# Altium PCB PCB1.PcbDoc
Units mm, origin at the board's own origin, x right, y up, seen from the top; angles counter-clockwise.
Board outline 78 x 70 mm, 2 copper layers (Top Layer, Bottom Layer); 42 components, 25 nets, 126 pads, 4 vias.
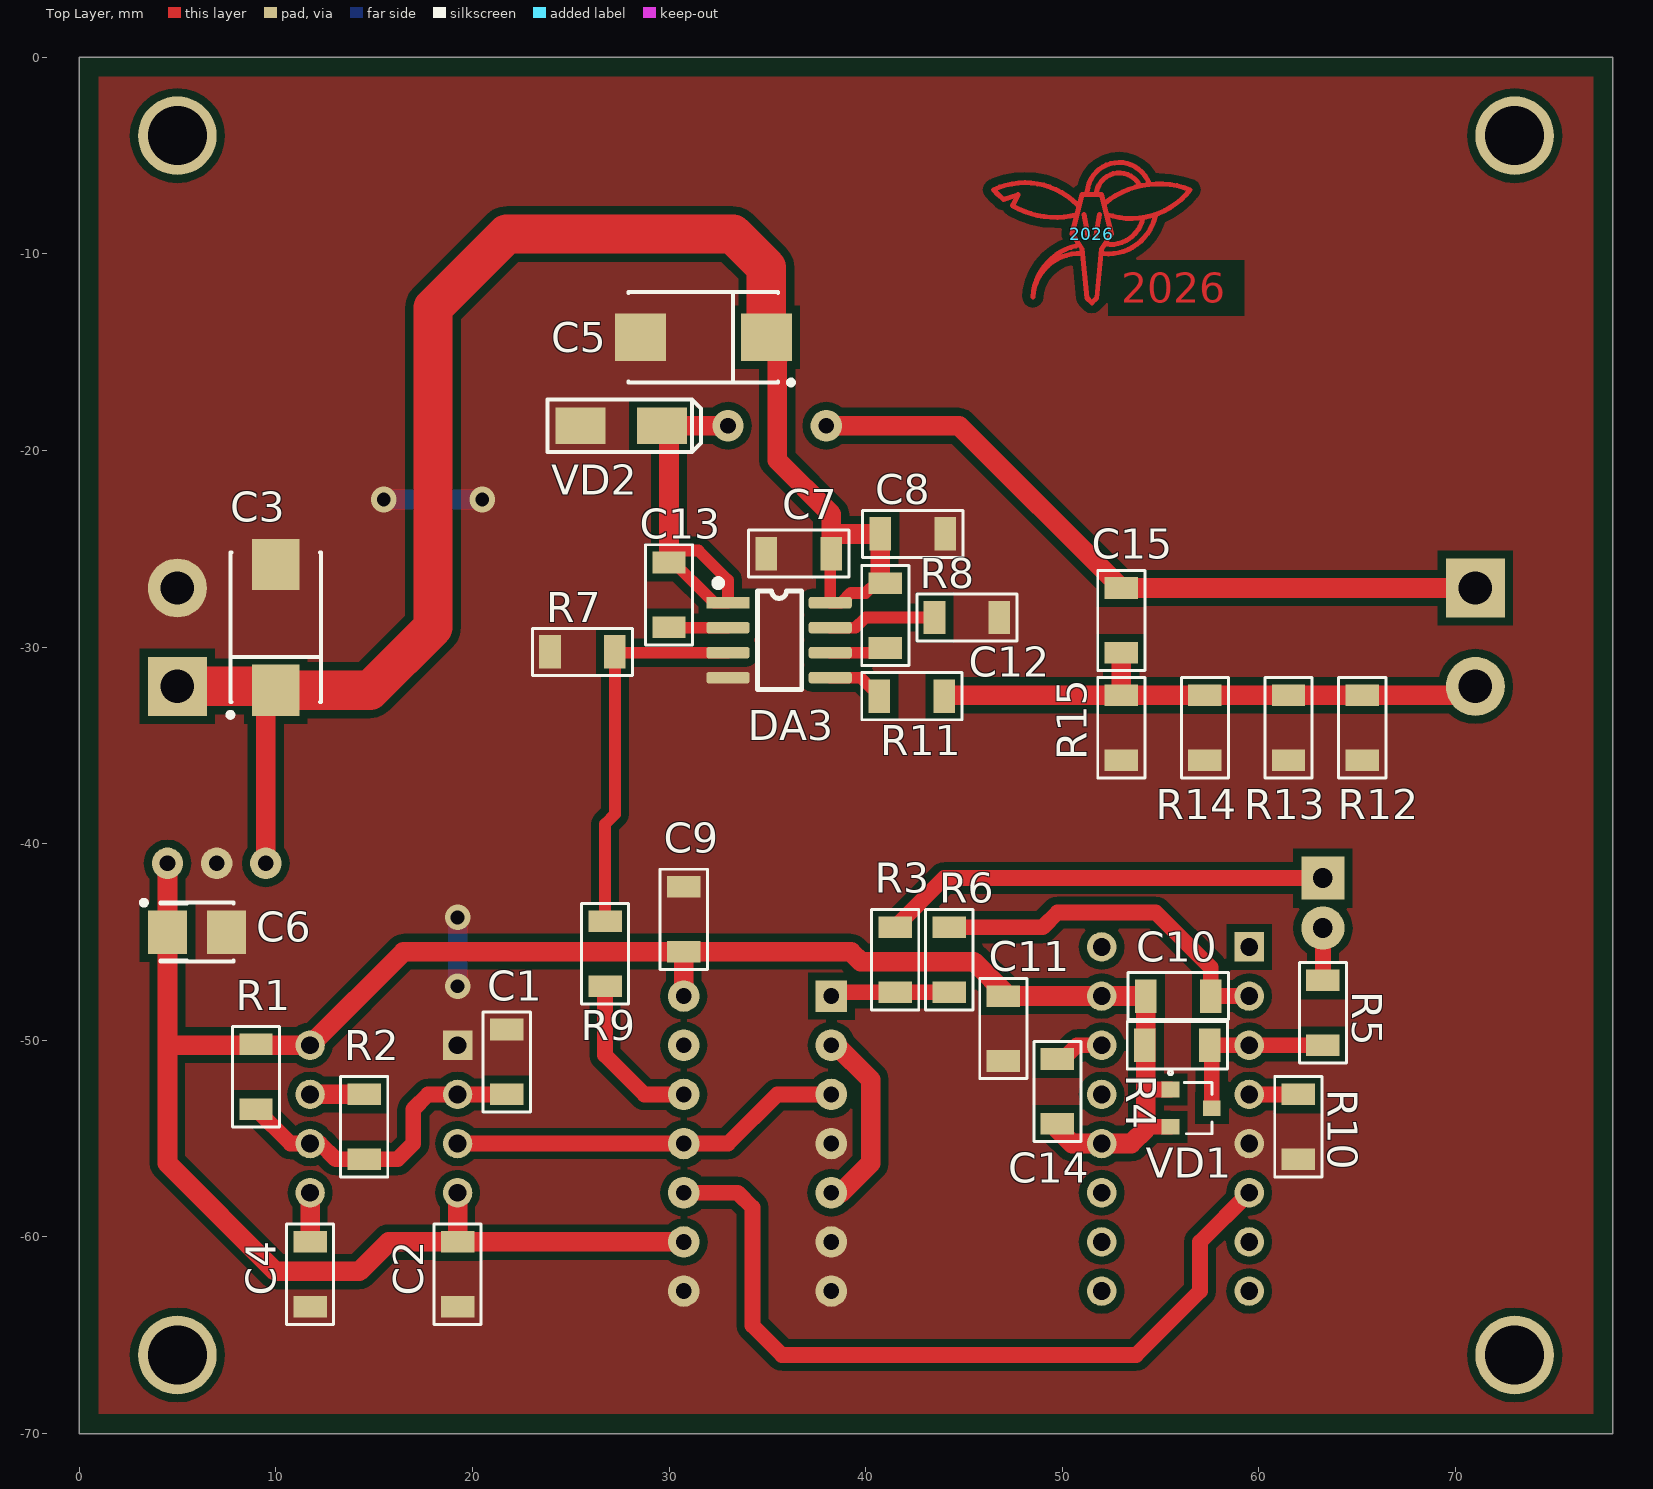
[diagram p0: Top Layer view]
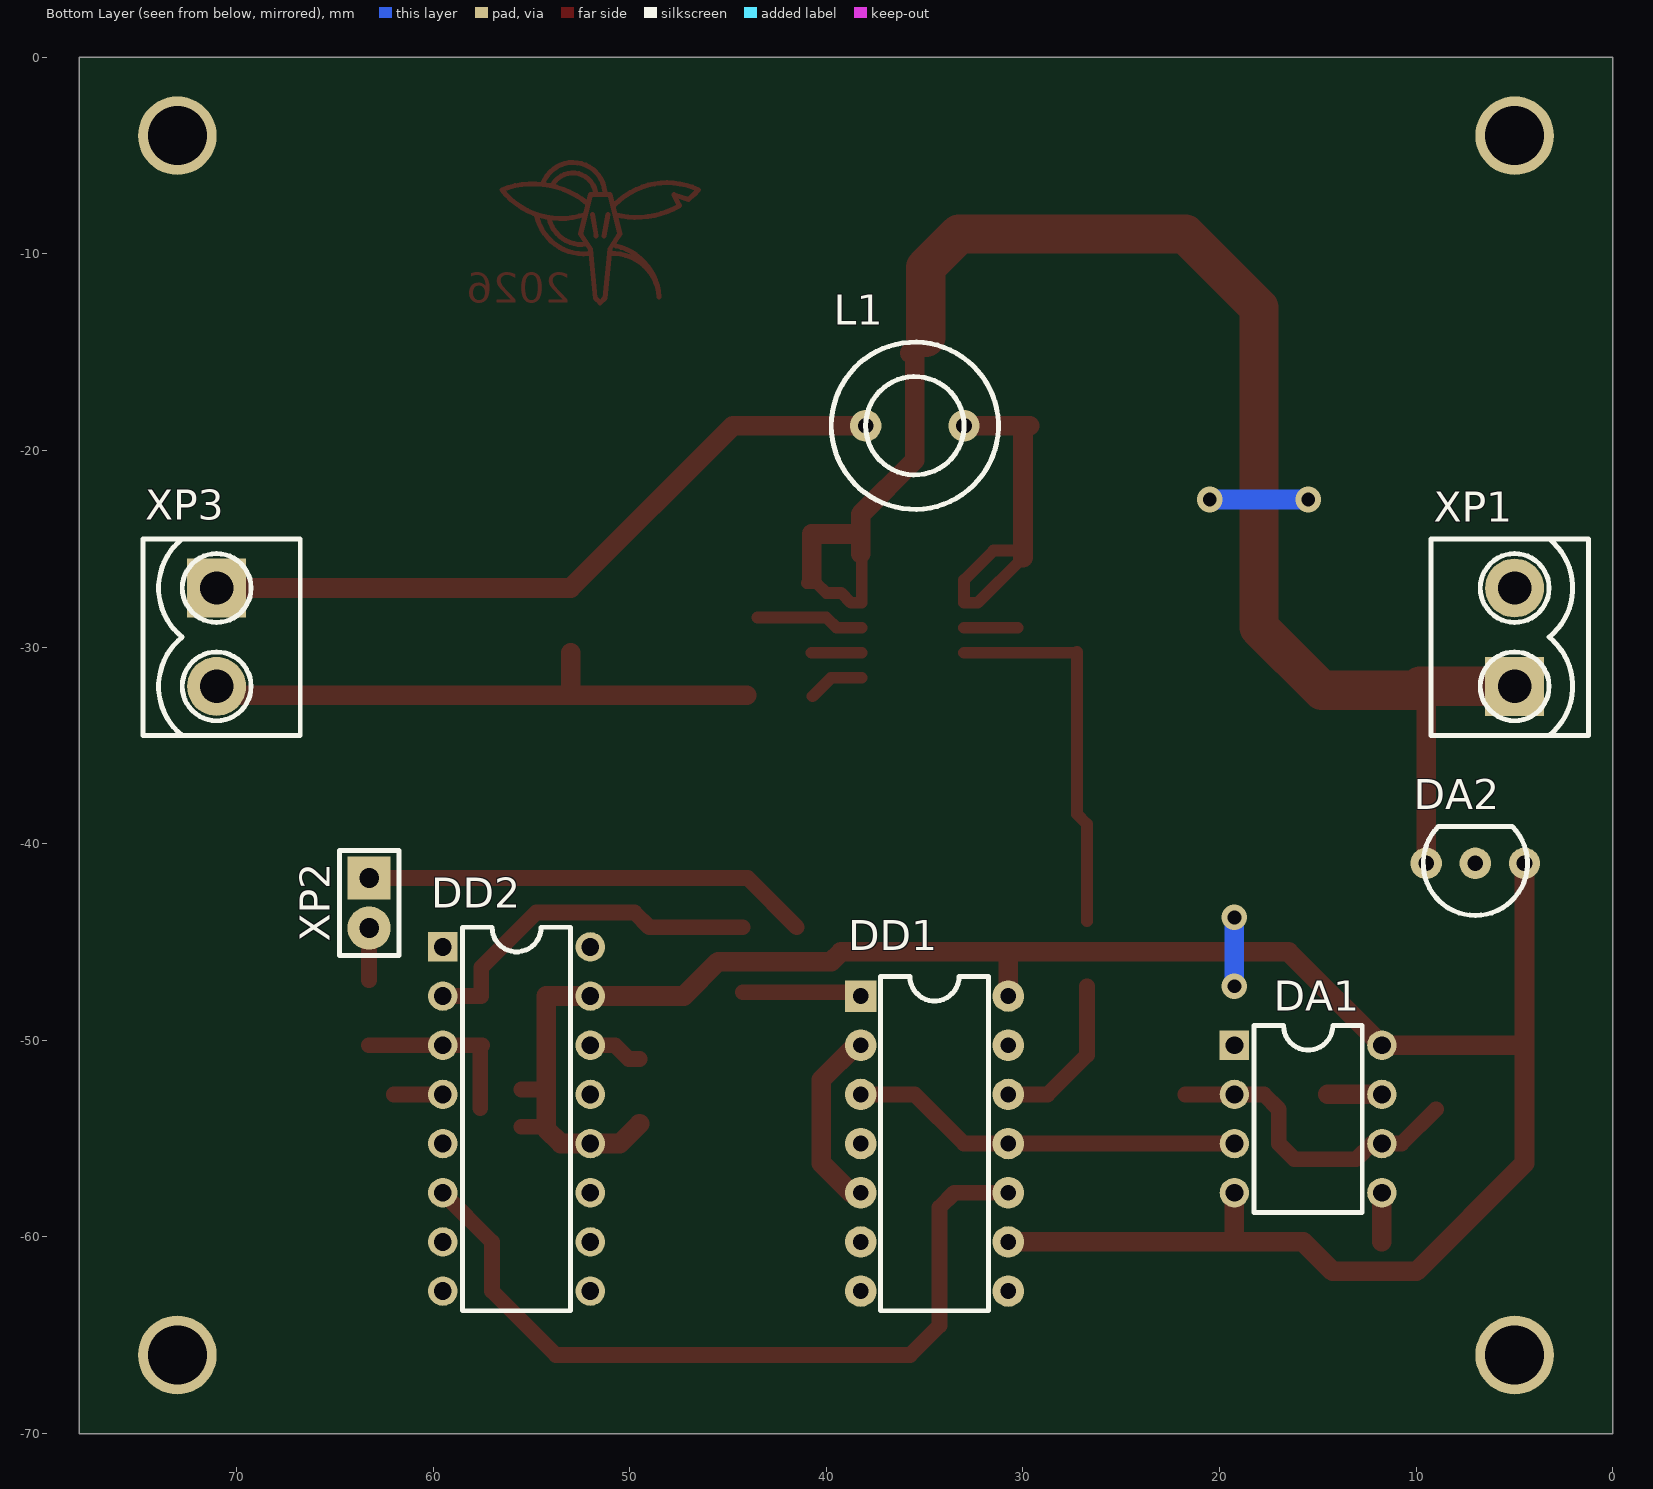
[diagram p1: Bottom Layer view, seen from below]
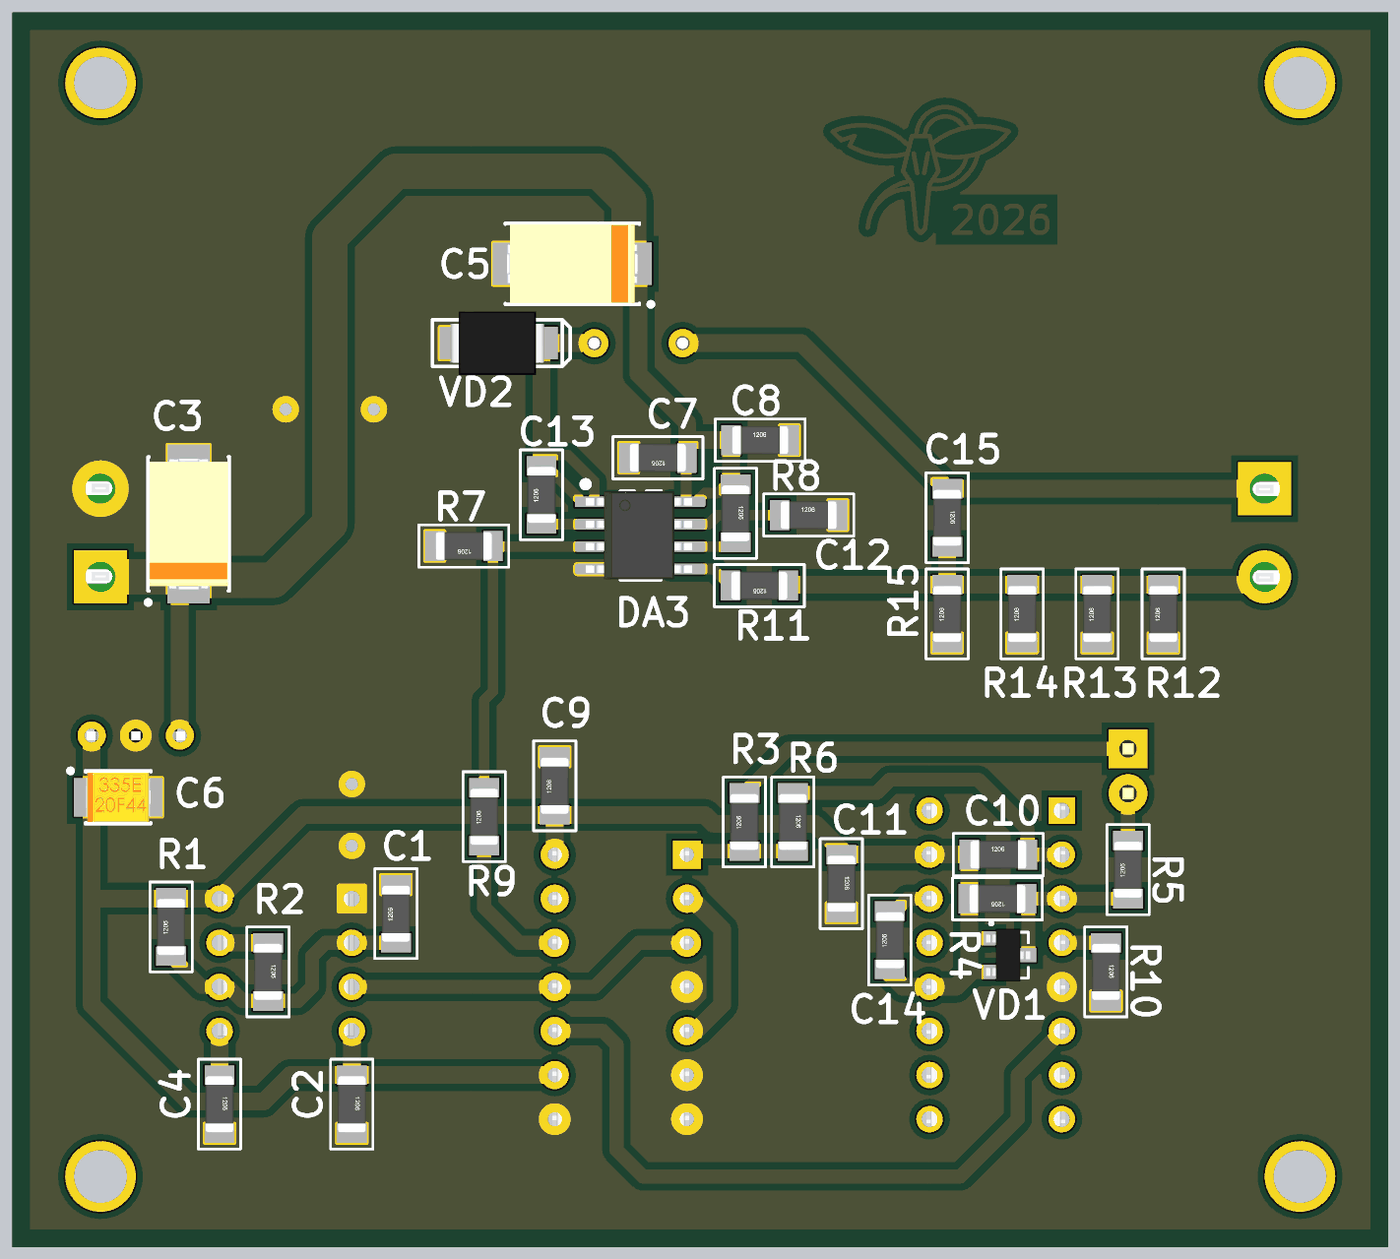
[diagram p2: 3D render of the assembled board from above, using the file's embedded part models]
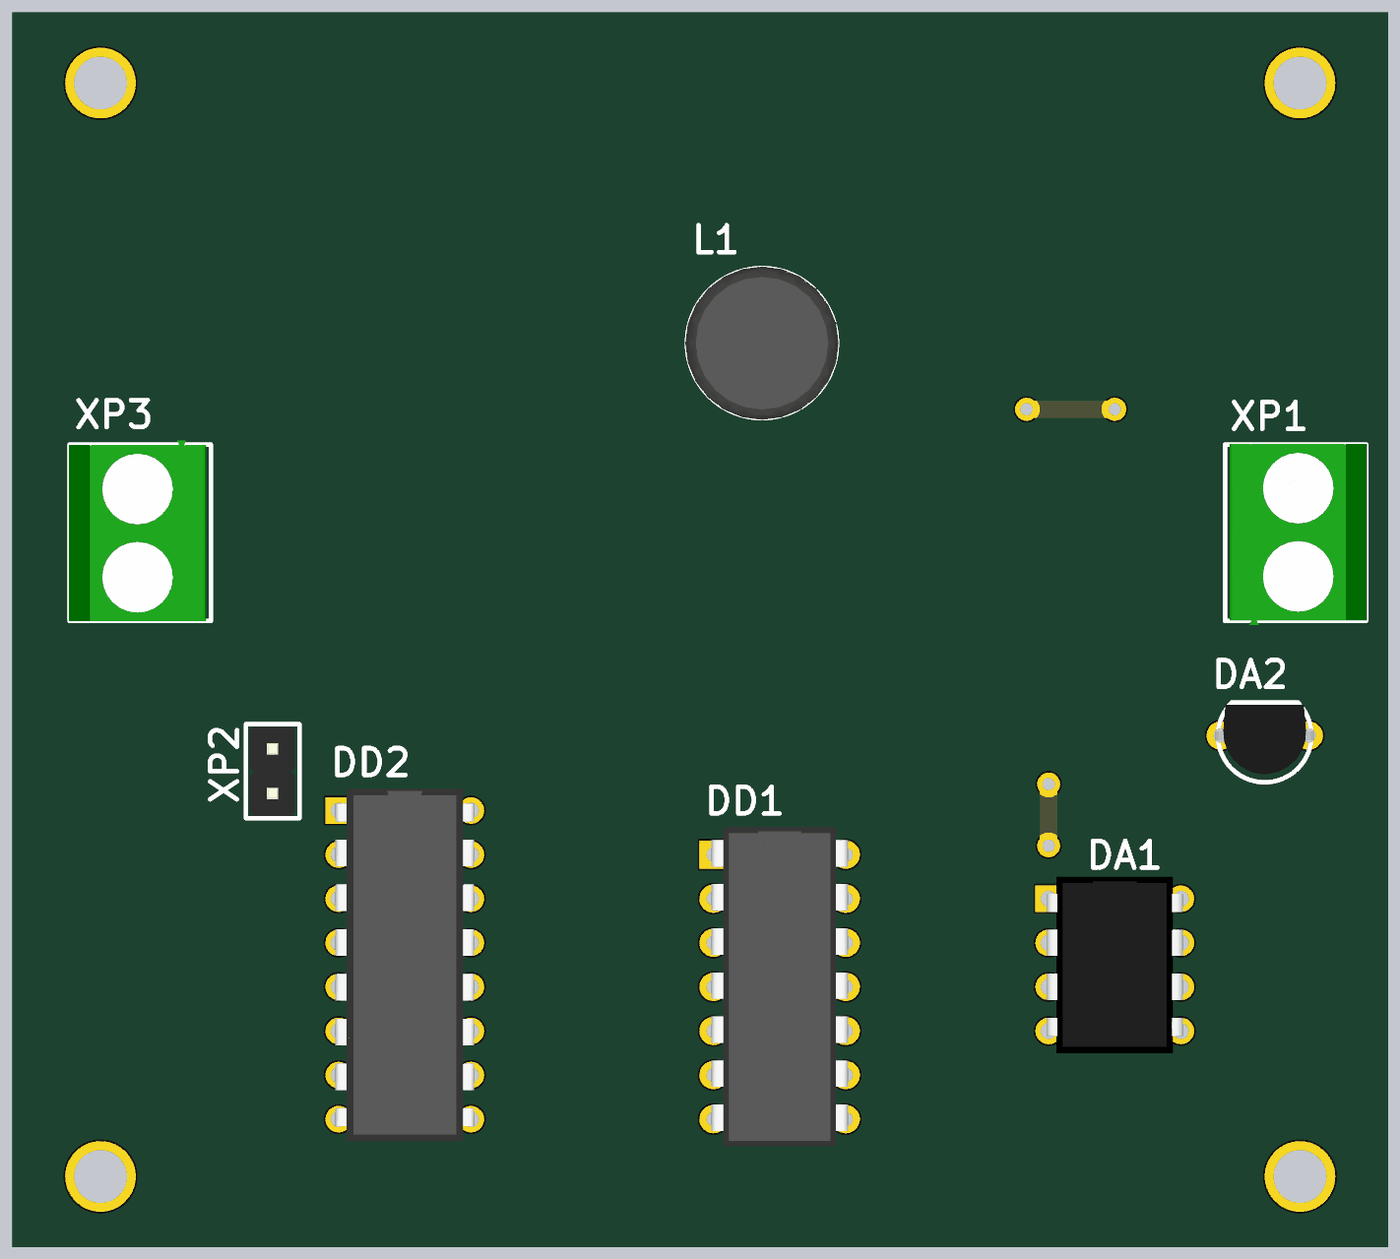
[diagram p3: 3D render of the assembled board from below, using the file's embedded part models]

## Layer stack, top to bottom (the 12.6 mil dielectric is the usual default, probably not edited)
Top Layer: signal copper 0.0356
Dielectric: dielectric 0.32, FR-4, Dk 4.8
Bottom Layer: signal copper 0.0356

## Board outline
0,0 78,0 78,-70 0,-70

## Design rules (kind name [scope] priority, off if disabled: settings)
Clearance Clearance_poly [InPolygon] p1: gap=0.4
Clearance [All] p2: gap=0.2
ComponentClearance [All] p1: gap=0.25 collisioncheckmode=3 verticalgap=0.25 showdistances=FALSE
DiffPairsRouting [All] p1: maxlimit=1 minlimit=0.2 mostfreqgap=0.8 maxuncoupledlength=10
Height [All] p1: minheight=0 maxheight=45 prefheight=12.5
PolygonConnect [All] p1: connectstyle=Direct reliefconductorwidth=0.35 reliefentries=4 polygonreliefangle="90 Angle"
RoutingVias [All] p1: holewidth=0.8 width=1.2 viastyle="Through Hole" minholewidth=0.7 minwidth=1 maxholewidth=1 maxwidth=1.5
SilkscreenOverComponentPads [All] p1: minsilkscreentomaskgap=0.254
SolderMaskExpansion [All] p1: expansion=0.102
Width [All] p1: maxlimit=3 minlimit=0.3 preferedwidth=0.5
24 further rules are at their usual default settings.

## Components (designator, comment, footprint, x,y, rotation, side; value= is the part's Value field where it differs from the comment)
2026 "2026" "Rat's logo" 51.5,-9 r0 top
C1 "C_1206" RC_1206 21.75,-52.75 r90 top
C2 "C_1206" RC_1206 19.25,-60.25 r270 top
C3 "Type D" "Type D" 10,-29 r90 top
C4 "C_1206" RC_1206 11.75,-60.25 r270 top
C5 "Type D" "Type D" 31.75,-14.25 r180 top
C6 "Type B" "Type B" 6,-44.5 r0 top
C7 "C_1206" RC_1206 38.25,-25.25 r180 top
C8 "C_1206" RC_1206 40.75,-24.25 r0 top
C9 "C_1206" RC_1206 30.75,-45.5 r90 top
C10 "C_1206" RC_1206 54.25,-47.75 r0 top
C11 "C_1206" RC_1206 47,-47.75 r270 top
C12 "C_1206" RC_1206 43.5,-28.5 r0 top
C13 "C_1206" RC_1206 30,-29 r90 top
C14 "C_1206" RC_1206 49.75,-54.25 r90 top
C15 "C_1206" RC_1206 53,-27 r270 top
DA1 "КР1006ВИ1" DIP-8-RU 15.5,-54 r180 bottom
DA2 "КР1157ЕН1502" TO-92 7,-41 r0 bottom
DA3 "LM3404MAX" SO-8 33,-27.75 r0 top
DD1 "К561ТМ2" DIP-14-RU 34.5,-55.25 r180 bottom
DD2 "К145АП2" DIP-16-RU 55.75,-54 r180 bottom
L1 "RLB0914" RLB0914 33,-18.75 r90 bottom
R1 "R_1206" RC_1206 9,-53.5 r90 top
R2 "R_1206" RC_1206 14.5,-52.75 r270 top
R3 "R_1206" RC_1206 41.5,-47.55 r90 top
R4 "R_1206" RC_1206 57.5,-50.25 r180 top
R5 "R_1206" RC_1206 63.25,-50.25 r90 top
R6 "R_1206" RC_1206 44.25,-44.25 r270 top
R7 "R_1206" RC_1206 27.25,-30.25 r180 top
R8 "R_1206" RC_1206 41,-26.75 r270 top
R9 "R_1206" RC_1206 26.75,-47.25 r90 top
R10 "R_1206" RC_1206 62,-52.75 r270 top
R11 "R_1206" RC_1206 44,-32.5 r180 top
R12 "R_1206" RC_1206 65.25,-35.75 r90 top
R13 "R_1206" RC_1206 61.5,-35.75 r90 top
R14 "R_1206" RC_1206 57.25,-35.75 r90 top
R15 "R_1206" RC_1206 53,-35.75 r90 top
VD1 "ESDA14V2L" SOT-23 55.5,-52.5 r270 top
VD2 "MBRS240" D-64 25.5,-18.75 r0 top
XP1 "Power" 2EDGV-2P 5,-32 r90 bottom
XP2 "Sensor" PLS-2 63.25,-41.75 r270 bottom
XP3 "Power" 2EDGV-2P 71,-27 r270 bottom

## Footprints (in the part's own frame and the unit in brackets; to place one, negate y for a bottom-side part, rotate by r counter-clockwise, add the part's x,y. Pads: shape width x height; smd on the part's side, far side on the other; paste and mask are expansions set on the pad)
2EDGV-2P [mm]
  rect 3x3 hole 1.7: 1(0,0)
  round 3 hole 1.7: 2(5,0)
  silkscreen extent -2.5,-3.75 7.5,4.25, body extent -2.72,-3.8 7.53,4, height 10.22
D-64 [mm]
  rect 2.55x1.85 smd: 1(0,0) 2(4.15,0)
  silkscreen extent -1.68,-1.33 6.12,1.33, body extent -0.65,-1.8 4.65,1.8, height 2.41
DIP-8-RU [mm]
  rect 1.5x1.5 hole 0.9: 1(-3.75,3.75)
  round 1.5 hole 0.9: 2(-3.75,1.25) 3(-3.75,-1.25) 4(-3.75,-3.75) 5(3.75,-3.75) 6(3.75,-1.25) 7(3.75,1.25) 8(3.75,3.75)
  silkscreen extent -2.75,-4.75 2.75,4.75, body extent -3.87,-5 3.88,5, height 5
DIP-14-RU [mm]
  rect 1.6x1.6 hole 0.8: 1(-3.75,7.5)
  round 1.6 hole 0.8: 2(-3.75,5) 3(-3.75,2.5) 4(-3.75,0) 5(-3.75,-2.5) 6(-3.75,-5) 7(-3.75,-7.5) 8(3.75,-7.5) 9(3.75,-5) 10(3.75,-2.5) 11(3.75,0) 12(3.75,2.5) 13(3.75,5) 14(3.75,7.5)
  silkscreen extent -2.75,-8.5 2.75,8.5, body extent -3.88,-9.05 3.88,9.05, height 4.5
DIP-16-RU [mm]
  rect 1.5x1.5 hole 0.9: 1(-3.75,8.75)
  round 1.5 hole 0.9: 2(-3.75,6.25) 3(-3.75,3.75) 4(-3.75,1.25) 5(-3.75,-1.25) 6(-3.75,-3.75) 7(-3.75,-6.25) 8(-3.75,-8.75) 9(3.75,-8.75) 10(3.75,-6.25) 11(3.75,-3.75) 12(3.75,-1.25) 13(3.75,1.25) 14(3.75,3.75) 15(3.75,6.25) 16(3.75,8.75)
  silkscreen extent -2.75,-9.75 2.75,9.75, body extent -3.93,-10 3.94,10, height 5.08
PLS-2 [mm]
  rect 2.2x2.2 hole 1: 1(0,0)
  round 2.2 hole 1: 2(2.54,0)
  silkscreen extent -1.4,-1.5 3.94,1.52, body extent -1.27,-1.27 3.81,1.27, height 8.54
"Rat's logo" [mm]
  Top Layer lines w0.254: -4.516,1.786 cw(c-1.875,5.025) -5,2.25 cw(c-3.402,-1.109) -0.75,1.5 ; -4.5,1.75 -3.75,2 -4,1.5 ; -4.033,1.446 ccw(c-1.875,5.025) -0.75,1 ; -0.8,-0.6 ccw(c-0.153,-3.378) -3,-3.2 cw(c-0.65,-3.35) -0.5,-1 ; -0.4,1 -0.2,-0.1 ; -0.238,2.147 cw(c1.384,2.012) 2.9,2.6 ; 0.2,-0.1 0.4,1 ; 0.239,2.148 cw(c1.394,1.929) 2.395,2.546 ; 0.6,-1 ccw(c0.831,1.445) 3.23,0.923 ; 0.652,1.562 cw(c3.411,-1.797) 5,2.25 cw(c2,4.6) 0.75,1 ; 0.711,-0.52 ccw(c0.937,1.169) 2.6,0.8 ; -1,0 -0.5,2 0.5,2 1,0 0.5,-0.75 0.25,-3.25 0,-3.5 -0.25,-3.25 -0.5,-0.75 -1,0
RC_1206 [mm]
  rect 1.1x1.7 smd: 1(0,0) 2(3.3,0)
  silkscreen extent -0.9,-1.2 4.2,1.2, body extent 0.05,-0.8 3.25,0.8, height 1
RLB0914 [mm]
  round 1.6 hole 0.8: 1(0,0) 2(0,5)
  silkscreen extent -4.25,-1.75 4.25,6.75, body extent -4.35,-1.85 4.35,6.85, height 10
SO-8 [mm]
  rect 2.2x0.6 smd: 1(0,0)
  rrect50% 2.2x0.6 smd: 2(0,-1.27) 3(0,-2.54) 4(0,-3.81) 5(5.2,-3.81) 6(5.2,-2.54) 7(5.2,-1.27) 8(5.2,0)
  silkscreen extent -0.6,-4.4 3.75,1.1, body extent -0.47,-4.4 5.54,0.6, height 1.75
SOT-23 [mm]
  rect 0.8x0.9 smd: 1(0,0) 2(1.9,0) 3(0.95,2.1)
  silkscreen extent -0.95,-0.1 2.25,2.1, body extent -0.55,-0.3 2.45,2.2, height 1.06
TO-92 [mm]
  round 1.6 hole 0.8: 1(-2.5,0) 2(0,0) 3(2.5,0)
  silkscreen extent -2.65,-1.88 2.65,2.65, body extent -2.8,-1.75 2.8,2.18, height 9.7
"Type B" [mm]
  rect 2x2.2 smd: 1(-1.5,0) 2(1.5,0)
  silkscreen extent -2.82,-1.5 1.85,1.62, body extent -1.83,-1.4 1.83,1.4, height 1.89
"Type D" [mm]
  rect 2.6x2.4 smd: 1(-3.2,0) 2(3.2,0)
  silkscreen extent -4.57,-2.3 3.8,2.42, body extent -3.7,-2.22 3.7,2.23, height 3

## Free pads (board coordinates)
  round 4 hole 3: 0(5,-66) 0(5,-4) 0(73,-66) 0(73,-4)

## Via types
v1: diameter 1.3, hole 0.7, Top Layer to Bottom Layer, 4 vias

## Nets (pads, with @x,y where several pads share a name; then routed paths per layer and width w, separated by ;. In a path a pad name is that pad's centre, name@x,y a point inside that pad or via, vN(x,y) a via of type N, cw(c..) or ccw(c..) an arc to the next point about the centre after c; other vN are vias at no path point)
GND: C1.2 C2.2 C3.2 C4.2 C5.2 C6.2 C7.2 C8.2 C9.2 C11.2 C12.2 DA1.1 DA2.2 DA3.4 DD1.4 DD1.6 DD1.7 DD1.8 DD2.5 R7.2 R10.2 R12.1 R13.1 R14.1 R15.1 VD2.1 XP1.2 | length 8.5
  Bottom Layer w1: v1(15.5,-22.5) v1(20.5,-22.5) ; v1(19.25,-47.25) v1(19.25,-43.75)
NetC1_1: C1.1 DA1.2 DA1.6 R1.1 R2.2 | length 16.2
  Top Layer w0.8: R1.1 10.75,-55.25 DA1.6 12.25,-55.25 13.05,-56.05 R2.2 16.2,-56.05 17,-55.25 17,-53.5 17.75,-52.75 C1.1
NetC3_1: C3.1 C5.1 C7.1 C8.1 DA2.3 DA3.8 R8.1 XP1.1 | length 83.6
  Top Layer w0.6: C7.1 38.2,-25.3 DA3.8 38.75,-27.75 39.25,-27.25 40,-27.25 40.5,-26.75 R8.1
  Top Layer w1: DA2.3 C3.1@9.5,-32.7 ; C3.1@9.8,-32 C3.1 ; C5.1@35.75,-15.05 35.5,-15.3 35.5,-20.5 38.25,-23.25 38.25,-24.25 ; C7.1 38.25,-24.25 ; R8.1@40.75,-26.5 C8.1 38.25,-24.25
  Top Layer w2: XP1.1 C3.1@9.8,-32 ; C3.1 14.8,-32.2 18,-29 18,-12.75 21.75,-9 33.25,-9 34.95,-10.7 C5.1
NetC4_1: C4.1 DA1.5 | length 2.5
  Top Layer w1: C4.1 DA1.5
NetC10_2: C10.2 DD2.2 R6.1 | length 18.2
  Top Layer w0.8: R6.1 49,-44.25 49.75,-43.5 54.75,-43.5 57.55,-46.3 C10.2 DD2.2
NetC12_1: C12.1 DA3.7 | length 5.5
  Top Layer w0.6: DA3.7 39.48,-29.02 40,-28.5 C12.1
NetC13_1: C13.1 DA3.2 | length 2.7
  Top Layer w0.6: C13.1@30.27,-29.02 DA3.2
NetC13_2: C13.2 DA3.1 L1.1 VD2.2 | length 18.4
  Top Layer w0.6: C13.2@30,-25.45 32.3,-27.75 DA3.1 33,-26.6 31.5,-25.1 30,-25.1
  Top Layer w1: VD2.2 L1.1 ; C13.2@30,-25.45 VD2.2@30,-19.1
NetC14_2: C14.2 DD2.14 | length 2.8
  Top Layer w0.8: C14.2@49.5,-50.95 50.05,-50.95 50.75,-50.25 DD2.14
NetC15_1: C15.1 L1.2 XP3.1 | length 36.4
  Top Layer w1: L1.2 44.75,-18.75 C15.1 XP3.1
NetC15_2: C15.2 R11.1 R12.2 R13.2 R14.2 R15.2 XP3.2 | length 28.7
  Top Layer w1: R11.1@44.05,-32.45 R15.2 ; C15.2 R15.2 ; XP3.2@70.55,-32.45 R12.2 R13.2 R14.2 R15.2
NetDA1_3: DA1.3 DD1.3 DD1.11 | length 20
  Top Layer w0.8: DA1.3 DD1.11 33,-55.25 35.5,-52.75 DD1.3
NetDA1_7: DA1.7 R2.1 | length 2.7
  Top Layer w1: DA1.7 R2.1
NetDA3_3: DA3.3 R7.1 R9.2 | length 19.6
  Top Layer w0.6: R9.2 26.75,-39 27.25,-38.5 R7.1 ; R7.1@27.29,-30.29 DA3.3
NetDA3_5: DA3.5 R11.2 | length 2.9
  Top Layer w0.6: DA3.5 39.76,-31.56 R11.2
NetDA3_6: DA3.6 R8.2 | length 2.6
  Top Layer w0.6: DA3.6 R8.2@40.76,-30.29
NetDD1_1: DD1.1 R3.1 R6.2 | length 6.1
  Top Layer w0.8: DD1.1 38.45,-47.55 R6.2
NetDD1_2: DD1.2 DD1.5 | length 9.6
  Top Layer w1: DD1.5 38.75,-57.75 40.25,-56.25 40.25,-52 38.5,-50.25 DD1.2
NetDD1_10: DD1.10 DD2.6 | length 40.6
  Top Layer w0.8: DD1.10 33.5,-57.75 34.25,-58.5 34.25,-64.5 35.75,-66 53.75,-66 57,-62.75 57,-60.25 DD2.6
NetDD1_12: DD1.12 R9.1 | length 8.3
  Top Layer w0.8: R9.1 26.75,-50.75 28.75,-52.75 DD1.12
NetDD2_3: DD2.3 R4.1 R5.1 VD1.3 | length 8.9
  Top Layer w0.8: R4.1 DD2.3 R5.1 ; VD1.3 R4.1@57.6,-50.35
NetDD2_4: DD2.4 R10.1 | length 2.5
  Top Layer w0.8: DD2.4 R10.1
NetR3_2: R3.2 XP2.1 | length 22.8
  Top Layer w0.8: R3.2 44,-41.75 XP2.1
NetR5_2: R5.2 XP2.2 | length 2.7
  Top Layer w0.8: R5.2 XP2.2
VCC: C2.1 C6.1 C9.1 C10.1 C11.1 C14.1 DA1.4 DA1.8 DA2.1 DD1.9 DD1.14 DD2.12 DD2.15 R1.2 R4.2 VD1.1 VD1.2 | length 116.4
  Top Layer w0.8: 54.25,-52.5 VD1.1 ; 54.35,-54.4 VD1.2
  Top Layer w1: DA2.1 C6.1 4.5,-50.25 ; DA1.4 C2.1 ; DD1.9 C2.1 ; DD1.14 C9.1 ; C14.1@49.5,-54.25 50.5,-55.25 DD2.12 53.5,-55.25 54.25,-54.5 54.25,-52.5 C10.1 DD2.15 47.25,-47.75 45.5,-46 39.75,-46 39.25,-45.5 C9.1 ; 4.5,-50.25 4.5,-56.25 10,-61.75 14.25,-61.75 15.75,-60.25 C2.1 ; 4.5,-50.25 DA1.8 16.5,-45.5 C9.1
pads on no net: DD1.13 DD2.1 DD2.7 DD2.8 DD2.9 DD2.10 DD2.11 DD2.13 DD2.16

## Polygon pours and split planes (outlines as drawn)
GND on Top Layer "Top Layer-GND" (solid, pour order 2): 1,-69 1,-1 77,-1 77,-69

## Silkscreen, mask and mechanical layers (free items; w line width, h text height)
Mechanical 32:
  the board outline again, w0.5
